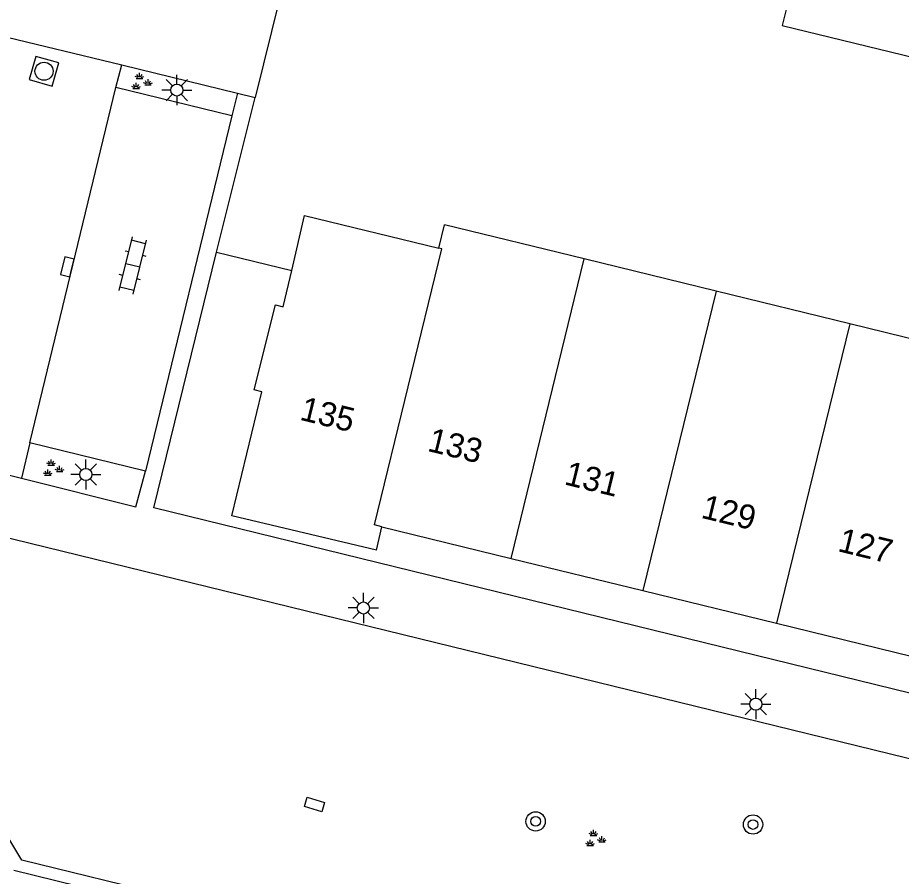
# Model space of a CAD drawing. Extents: x 125000 to 129004, y 397500 to 399008.
# Drawn here: x 126229.84 to 126266.44, y 398155.04 to 398190.63 of the extents above; entities that cross this region are included whole.
import ezdxf

# ---------------------------------------------------------------- set-up
doc = ezdxf.new("R2010")
doc.units = 0
for name, color, linetype in [('gg-afsc-hekwerk', 7, 'Continuous'), ('gg-anno-huisnummerreeks BGT', 7, 'Continuous'), ('gg-bbg-gedigitaliseerde bijgebouw', 7, 'Continuous'), ('gg-bbg-hoofdgebouw', 7, 'Continuous'), ('gg-bbg-tussenscheiding', 7, 'Continuous'), ('gg-knt-verharding', 7, 'Continuous'), ('gt-grn-weggrens', 7, 'Continuous'), ('gt-symb-boom', 7, 'Continuous'), ('gt-symb-groenvak', 7, 'Continuous'), ('gt-symb-klinker verharding', 7, 'Continuous'), ('gt-symb-kolk', 7, 'Continuous'), ('gt-symb-kolk center center', 7, 'Continuous'), ('gt-symb-lichtmast', 7, 'Continuous'), ('gt-symb-rioolschacht', 7, 'Continuous')]:
    doc.layers.add(name, color=color, linetype=linetype)

# ---------------------------------------------------------------- blocks, each defined once
blk = doc.blocks.new('gt0-RS')
at = {"layer": 'gt-symb-rioolschacht'}
blk.add_lwpolyline([(-0.5, -0.5), (0.5, -0.5), (0.5, 0.5), (-0.5, 0.5)], close=True, dxfattribs=at)
blk.add_circle((0, 0), 0.375, dxfattribs=at)
blk = doc.blocks.new('gt0-KL1')
at = {"layer": 'gt-symb-klinker verharding'}
for p, q in [((-0.5, 0.3), (-0.5, 0.45)), ((0.5, 0.3), (0.5, 0.45)), ((-1.15, 0.3), (1.15, 0.3)), ((-1, -0.3), (-1, 0.3)), ((0, -0.3), (0, 0.3)), ((1, -0.3), (1, 0.3)), ((-1.15, -0.3), (1.15, -0.3)), ((-0.5, -0.45), (-0.5, -0.3)), ((0.5, -0.45), (0.5, -0.3))]:
    blk.add_line(p, q, dxfattribs=at)
blk = doc.blocks.new('gt0-LMAST')
at = {"layer": 'gt-symb-lichtmast'}
for p, q in [((-0.182, 0.173), (-0.447, 0.438)), ((-0.005, 0.246), (-0.005, 0.621)), ((0.172, 0.173), (0.437, 0.438)), ((-0.255, -0.004), (-0.63, -0.004)), ((-0.182, -0.181), (-0.447, -0.446)), ((-0.005, -0.254), (-0.005, -0.629)), ((0.437, -0.446), (0.172, -0.181)), ((0.245, -0.004), (0.62, -0.004))]:
    blk.add_line(p, q, dxfattribs=at)
blk.add_circle((-0.005, -0.004), 0.25, dxfattribs=at)
blk = doc.blocks.new('gt0-GRVAK')
at = {"layer": 'gt-symb-groenvak'}
for p, q in [((-0.047, 0.214), (-0.047, 0.393)), ((-0.11, 0.189), (-0.228, 0.24)), ((-0.182, 0.153), (0.088, 0.153)), ((-0.091, 0.211), (-0.156, 0.322)), ((-0.004, 0.211), (0.061, 0.322)), ((0.015, 0.189), (0.133, 0.24)), ((0.262, -0.052), (0.197, 0.059)), ((0.305, -0.049), (0.305, 0.13)), ((0.349, -0.052), (0.414, 0.059)), ((-0.245, -0.228), (-0.363, -0.177)), ((-0.318, -0.264), (-0.047, -0.264)), ((-0.226, -0.206), (-0.291, -0.095)), ((-0.183, -0.203), (-0.183, -0.024)), ((-0.139, -0.206), (-0.074, -0.095)), ((-0.12, -0.228), (-0.002, -0.177)), ((0.243, -0.074), (0.125, -0.023)), ((0.17, -0.11), (0.441, -0.11)), ((0.368, -0.074), (0.486, -0.023))]:
    blk.add_line(p, q, dxfattribs=at)
blk = doc.blocks.new('gt0-KOLK')
at = {"layer": 'gt-symb-kolk'}
blk.add_lwpolyline([(0, 0), (0.375, 0), (0.375, 0.4), (-0.375, 0.4), (-0.375, 0), (0, 0)], dxfattribs=at)
blk = doc.blocks.new('gt0-KOLKCC')
at = {"layer": 'gt-symb-kolk center center'}
blk.add_lwpolyline([(-0.375, 0.2), (0.375, 0.2), (0.375, -0.2), (-0.375, -0.2)], close=True, dxfattribs=at)
blk = doc.blocks.new('gt0-BOOM')
at = {"layer": 'gt-symb-boom'}
for radius in [0.4, 0.2]:
    blk.add_circle((0, 0), radius, dxfattribs=at)

msp = doc.modelspace()

# ---------------------------------------------------------------- linework, layer by layer
at = {"layer": 'gg-afsc-hekwerk'}
for p, q in [((126241.941, 398196.427), (126239.671, 398187.328)), ((126238.071, 398180.917), (126239.671, 398187.328)), ((126238.071, 398180.917), (126241.195, 398180.159))]:
    msp.add_line(p, q, dxfattribs=at)
at = {"layer": 'gg-bbg-gedigitaliseerde bijgebouw'}
msp.add_lwpolyline([(126261.702, 398191.086), (126261.512, 398190.309), (126267.011, 398188.966), (126267.318, 398190.224)], dxfattribs=at)
at = {"layer": 'gg-bbg-hoofdgebouw'}
for p, q in [((126247.28, 398181.082), (126247.518, 398182.053)), ((126253.312, 398180.635), (126247.518, 398182.053)), ((126258.769, 398179.301), (126253.312, 398180.635)), ((126264.306, 398177.946), (126258.769, 398179.301)), ((126269.939, 398176.568), (126264.306, 398177.946)), ((126244.699, 398168.567), (126244.928, 398169.53)), ((126244.928, 398169.53), (126250.283, 398168.222)), ((126250.283, 398168.222), (126255.733, 398166.89)), ((126255.733, 398166.89), (126261.27, 398165.537)), ((126261.27, 398165.537), (126266.904, 398164.16))]:
    msp.add_line(p, q, dxfattribs=at)
for points in [[(126241.195, 398180.159), (126241.726, 398182.434), (126247.28, 398181.082)], [(126244.699, 398168.567), (126238.711, 398169.988), (126239.956, 398175.13), (126239.635, 398175.207), (126240.522, 398178.729), (126240.842, 398178.648), (126241.195, 398180.159)]]:
    msp.add_lwpolyline(points, dxfattribs=at)
at = {"layer": 'gg-bbg-tussenscheiding'}
for p, q in [((126250.283, 398168.222), (126253.312, 398180.635)), ((126258.769, 398179.301), (126255.733, 398166.89)), ((126264.306, 398177.946), (126261.27, 398165.537))]:
    msp.add_line(p, q, dxfattribs=at)
msp.add_lwpolyline([(126244.928, 398169.53), (126244.617, 398169.606), (126247.41, 398181.05), (126247.28, 398181.082)], dxfattribs=at)
at = {"layer": 'gg-knt-verharding'}
for p, q in [((126233.899, 398187.734), (126234.149, 398188.682)), ((126234.149, 398188.682), (126238.949, 398187.505)), ((126230.337, 398173.013), (126233.899, 398187.734)), ((126238.711, 398186.564), (126233.899, 398187.734)), ((126238.949, 398187.505), (126238.711, 398186.564)), ((126238.711, 398186.564), (126235.128, 398171.843)), ((126230.337, 398173.013), (126229.993, 398171.548)), ((126235.128, 398171.843), (126230.337, 398173.013)), ((126228.531, 398169.295), (126282.716, 398156.022)), ((126275.162, 398144.701), (126230.006, 398155.716)), ((126270.623, 398145.294), (126229.685, 398155.28))]:
    msp.add_line(p, q, dxfattribs=at)
for points in [[(126278.223, 398159.833), (126235.481, 398170.323), (126238.071, 398180.917)], [(126229.993, 398171.548), (126234.728, 398170.361), (126235.128, 398171.843)], [(126230.006, 398155.716), (126226.628, 398161.319), (126228.531, 398169.295)]]:
    msp.add_lwpolyline(points, dxfattribs=at)
at = {"layer": 'gt-grn-weggrens'}
for p, q in [((126227.935, 398190.179), (126234.149, 398188.682)), ((126238.949, 398187.505), (126239.671, 398187.328)), ((126223.766, 398173.059), (126229.993, 398171.548))]:
    msp.add_line(p, q, dxfattribs=at)

# ---------------------------------------------------------------- block references
at = {"layer": 'gt-symb-boom'}
for p in [(126251.296, 398157.321), (126260.301, 398157.191)]:
    msp.add_blockref('gt0-BOOM', p, dxfattribs=at)
at = {"layer": 'gt-symb-groenvak'}
for p in [(126234.933, 398187.958), (126231.273, 398171.934), (126253.738, 398156.581)]:
    msp.add_blockref('gt0-GRVAK', p, dxfattribs=at)
at = {"layer": 'gt-symb-klinker verharding', "rotation": 75.93596328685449}
msp.add_blockref('gt0-KL1', (126234.607, 398180.363), dxfattribs=at)
at = {"layer": 'gt-symb-kolk', "rotation": 76.40843956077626}
msp.add_blockref('gt0-KOLK', (126232.089, 398180.257), dxfattribs=at)
at = {"layer": 'gt-symb-kolk center center', "rotation": -16.8035480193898}
msp.add_blockref('gt0-KOLKCC', (126242.133, 398158.021), dxfattribs=at)
at = {"layer": 'gt-symb-lichtmast'}
for p in [(126236.439, 398187.636), (126232.67, 398171.702), (126244.164, 398166.17), (126260.423, 398162.183)]:
    msp.add_blockref('gt0-LMAST', p, dxfattribs=at)
at = {"layer": 'gt-symb-rioolschacht', "rotation": 73.97589034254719}
msp.add_blockref('gt0-RS', (126230.931, 398188.411), dxfattribs=at)

# ---------------------------------------------------------------- texts
at = {"layer": 'gg-anno-huisnummerreeks BGT'}
for s, p in [('135', (126241.484, 398173.974)), ('133', (126246.776, 398172.681)), ('131', (126252.441, 398171.296)), ('129', (126258.107, 398169.912)), ('127', (126263.772, 398168.527))]:
    msp.add_text(s, height=1, rotation=346.3, dxfattribs=at).set_placement(p)

doc.saveas('drawing.dxf')
